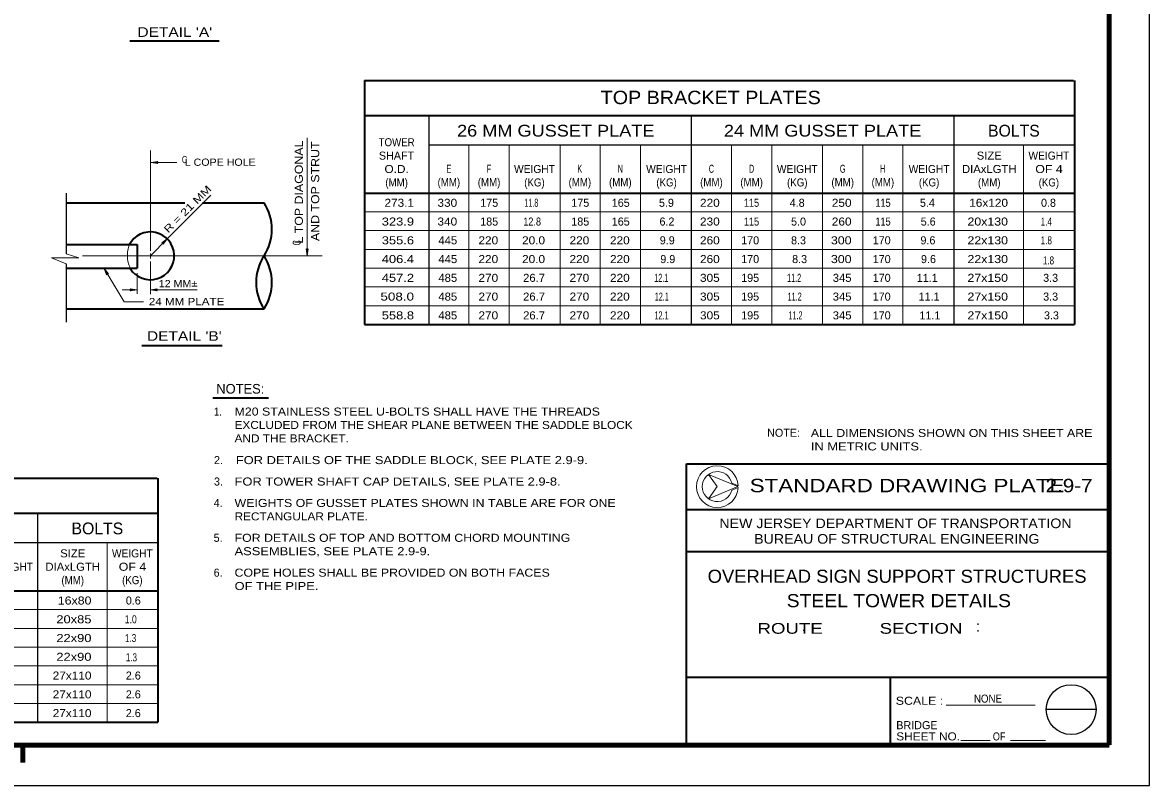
# Model space of a CAD drawing. Extents: x 312601.858 to 312602.699, y 144420.109 to 144420.704.
# Drawn here: x 312602.2782 to 312602.6988, y 144420.1095 to 144420.3942 of the extents above; entities that cross this region are included whole.
import ezdxf
from ezdxf.enums import TextEntityAlignment as Align

# ---------------------------------------------------------------- set-up
doc = ezdxf.new("R2010")
doc.units = 0
doc.header["$LTSCALE"] = 0.0012
doc.linetypes.add('DOT_DASHED', pattern=[7.7, 5, -1.2, 0.3, -1.2])
doc.linetypes.add('DOTTED', pattern=[1.5, 0.3, -1.2])
for name, color, linetype, lineweight in [('1', 7, 'Continuous', 25), ('2', 7, 'Continuous', 13), ('39', 7, 'Continuous', 13)]:
    doc.layers.add(name, color=color, linetype=linetype, lineweight=lineweight)
doc.layers.add('4', color=7, linetype='Continuous')

msp = doc.modelspace()

# ---------------------------------------------------------------- hatches: boundary and pattern name
at = {"layer": '39'}
for points in [[(312602.3284, 144420.3419), (312602.3287, 144420.3415), (312602.3261, 144420.3419), (312602.3287, 144420.3423)], [(312602.3306, 144420.3118), (312602.3301, 144420.3119), (312602.3322, 144420.3135), (312602.3307, 144420.3114)], [(312602.3844, 144420.3094), (312602.3848, 144420.3097), (312602.3844, 144420.3071), (312602.384, 144420.3097)], [(312602.3098, 144420.3004), (312602.3095, 144420.3), (312602.3086, 144420.3024), (312602.3102, 144420.3004)], [(312602.3186, 144420.2944), (312602.3184, 144420.2948), (312602.3209, 144420.2944), (312602.3184, 144420.294)], [(312602.3186, 144420.2944), (312602.3184, 144420.2948), (312602.3209, 144420.2944), (312602.3184, 144420.294)], [(312602.3282, 144420.2944), (312602.3284, 144420.294), (312602.3259, 144420.2944), (312602.3284, 144420.2948)]]:
    msp.add_hatch(color=256, dxfattribs=at).paths.add_polyline_path(points)

# ---------------------------------------------------------------- linework, layer by layer
at = {"layer": '1', "lineweight": 13}
for p, q in [((312602.3844, 144420.3511), (312602.3844, 144420.3071)), ((312602.3259, 144420.3464), (312602.3259, 144420.309)), ((312602.3357, 144420.3419), (312602.3262, 144420.3419)), ((312602.3259, 144420.308), (312602.3259, 144420.3061)), ((312602.3812, 144420.3071), (312602.3871, 144420.3071)), ((312602.3161, 144420.2899), (312602.3086, 144420.3024)), ((312602.3259, 144420.305), (312602.3259, 144420.2928)), ((312602.3209, 144420.3007), (312602.3209, 144420.2929)), ((312602.3209, 144420.2944), (312602.3154, 144420.2944)), ((312602.3433, 144420.2944), (312602.3259, 144420.2944)), ((312602.3434, 144420.2958), (312602.3414, 144420.2958)), ((312602.3233, 144420.2899), (312602.3161, 144420.2899)), ((312602.543, 144420.2197), (312602.5453, 144420.2207))]:
    msp.add_line(p, q, dxfattribs=at)
at = {"layer": '1'}
for p, q in [((312602.2944, 144420.3305), (312602.2944, 144420.3079)), ((312602.2944, 144420.3041), (312602.2944, 144420.2823))]:
    msp.add_line(p, q, dxfattribs=at)
at = {"layer": '1', "lineweight": 35}
for p, q in [((312602.2944, 144420.3269), (312602.3387, 144420.3269)), ((312602.3453, 144420.3269), (312602.3683, 144420.3269)), ((312602.2944, 144420.3113), (312602.3209, 144420.3113)), ((312602.3209, 144420.3113), (312602.3209, 144420.3025)), ((312602.2944, 144420.3025), (312602.3209, 144420.3025)), ((312602.2944, 144420.2873), (312602.3683, 144420.2873))]:
    msp.add_line(p, q, dxfattribs=at)
at = {"layer": '1', "linetype": 'DOT_DASHED', "lineweight": 13}
msp.add_line((312602.3005, 144420.3071), (312602.39, 144420.3071), dxfattribs=at)
at = {"layer": '1', "lineweight": 158}
msp.add_line((312602.2783, 144420.1181), (312602.2783, 144420.1245), dxfattribs=at)
at = {"layer": '1', "lineweight": 13}
for points in [[(312602.3259, 144420.3071), (312602.3322, 144420.3135), (312602.3484, 144420.3297)], [(312602.2944, 144420.3041), (312602.289, 144420.3063), (312602.2992, 144420.3063), (312602.2944, 144420.3079)], [(312602.5451, 144420.221), (312602.5342, 144420.2255), (312602.5451, 144420.221)], [(312602.5453, 144420.2213), (312602.543, 144420.2223), (312602.5429, 144420.2223)]]:
    msp.add_lwpolyline(points, dxfattribs=at)
for points in [[(312602.5451, 144420.221), (312602.5342, 144420.2255), (312602.5374, 144420.221), (312602.5342, 144420.2165)], [(312602.5374, 144420.221), (312602.5342, 144420.2165), (312602.5451, 144420.221), (312602.5342, 144420.2255)]]:
    msp.add_lwpolyline(points, close=True, dxfattribs=at)
at = {"layer": '1', "lineweight": 35}
for centre, radius, start, end in [((312602.353043, 144420.317), 0.018187, 327.02071, 32.97929), ((312602.3259, 144420.3071), 0.008914, 212.2085, 152.57299), ((312602.383557, 144420.2972), 0.018187, 147.02071, 212.97929), ((312602.353043, 144420.2972), 0.018187, 327.02071, 32.97929)]:
    msp.add_arc(centre, radius, start, end, dxfattribs=at)
at = {"layer": '1', "linetype": 'DOTTED', "lineweight": 13}
msp.add_arc((312602.328025, 144420.307233), 0.010726, 157.7196, 206.18542, dxfattribs=at)
at = {"layer": '1', "lineweight": 13}
for radius, start, end in [(0.007803, 2.21392, 357.78608), (0.0056, 13.69411, 346.30589)]:
    msp.add_arc((312602.5375, 144420.221), radius, start, end, dxfattribs=at)
at = {"layer": '2', "lineweight": 35}
for p, q in [((312602.3182, 144420.3873), (312602.3516, 144420.3873)), ((312602.4058, 144420.3725), (312602.4058, 144420.2815)), ((312602.4058, 144420.3725), (312602.6705, 144420.3725)), ((312602.6708, 144420.3725), (312602.6708, 144420.2815)), ((312602.4058, 144420.3595), (312602.6708, 144420.3595)), ((312602.4058, 144420.3305), (312602.6708, 144420.3305)), ((312602.4058, 144420.2815), (312602.6708, 144420.2815)), ((312602.3227, 144420.2737), (312602.3527, 144420.2737)), ((312602.37, 144420.254), (312602.3492, 144420.254)), ((312602.0147, 144420.2241), (312602.3284, 144420.2241)), ((312602.3287, 144420.2241), (312602.3287, 144420.1331)), ((312602.0147, 144420.2111), (312602.3287, 144420.2111)), ((312602.0147, 144420.1821), (312602.3287, 144420.1821)), ((312602.0147, 144420.1331), (312602.3287, 144420.1331))]:
    msp.add_line(p, q, dxfattribs=at)
at = {"layer": '2'}
for p, q in [((312602.4058, 144420.3725), (312602.4058, 144420.2815)), ((312602.4448, 144420.3485), (312602.4448, 144420.2815)), ((312602.4598, 144420.3485), (312602.4598, 144420.2815)), ((312602.4788, 144420.3485), (312602.4788, 144420.2815)), ((312602.4938, 144420.3485), (312602.4938, 144420.2815)), ((312602.5088, 144420.3485), (312602.5088, 144420.2815)), ((312602.5428, 144420.3485), (312602.5428, 144420.2815)), ((312602.5578, 144420.3485), (312602.5578, 144420.2815)), ((312602.5768, 144420.3485), (312602.5768, 144420.2815)), ((312602.5918, 144420.3485), (312602.5918, 144420.2815)), ((312602.6068, 144420.3485), (312602.6068, 144420.2815)), ((312602.6518, 144420.3485), (312602.6518, 144420.2815)), ((312602.4058, 144420.3235), (312602.6708, 144420.3235)), ((312602.4058, 144420.3165), (312602.6708, 144420.3165)), ((312602.4058, 144420.3095), (312602.6705, 144420.3095)), ((312602.4058, 144420.3025), (312602.6708, 144420.3025)), ((312602.4058, 144420.2955), (312602.6708, 144420.2955)), ((312602.4058, 144420.2885), (312602.6708, 144420.2885)), ((312602.3097, 144420.2001), (312602.3097, 144420.1331)), ((312602.0147, 144420.1751), (312602.3287, 144420.1751)), ((312602.0147, 144420.1681), (312602.3287, 144420.1681)), ((312602.0147, 144420.1611), (312602.3284, 144420.1611)), ((312602.0147, 144420.1541), (312602.3287, 144420.1541)), ((312602.0147, 144420.1471), (312602.3287, 144420.1471)), ((312602.0147, 144420.1401), (312602.3287, 144420.1401))]:
    msp.add_line(p, q, dxfattribs=at)
at = {"layer": '2', "lineweight": 25}
for p, q in [((312602.4298, 144420.3595), (312602.4298, 144420.2815)), ((312602.5278, 144420.3595), (312602.5278, 144420.2815)), ((312602.6258, 144420.3595), (312602.6258, 144420.2815)), ((312602.4298, 144420.3485), (312602.6708, 144420.3485)), ((312602.2837, 144420.2111), (312602.2837, 144420.1331)), ((312602.0387, 144420.2001), (312602.3287, 144420.2001))]:
    msp.add_line(p, q, dxfattribs=at)
at = {"layer": '39', "lineweight": 25}
for p, q in [((312602.6988, 144420.1095), (312602.6988, 144420.7035)), ((312602.6789, 144420.1378), (312602.6603, 144420.1378)), ((312602.452, 144420.1245), (312602.6838, 144420.1245)), ((312601.8578, 144420.1095), (312602.6988, 144420.1095))]:
    msp.add_line(p, q, dxfattribs=at)
at = {"layer": '39', "lineweight": 158}
for p, q in [((312602.6838, 144420.1247), (312602.6838, 144420.6645)), ((312601.9088, 144420.1245), (312602.6838, 144420.1245)), ((312602.2783, 144420.1181), (312602.2783, 144420.1245))]:
    msp.add_line(p, q, dxfattribs=at)
at = {"layer": '39', "lineweight": 35}
for p, q in [((312602.526, 144420.1245), (312602.526, 144420.2295)), ((312602.526, 144420.2295), (312602.6838, 144420.2295)), ((312602.6838, 144420.2295), (312602.6838, 144420.1245)), ((312602.526, 144420.2124), (312602.6838, 144420.2124)), ((312602.526, 144420.1968), (312602.6838, 144420.1968)), ((312602.526, 144420.1499), (312602.6838, 144420.1499)), ((312602.6022, 144420.1248), (312602.6022, 144420.1499))]:
    msp.add_line(p, q, dxfattribs=at)
at = {"layer": '39'}
for p, q in [((312602.6022, 144420.1499), (312602.6838, 144420.1499)), ((312602.6022, 144420.1248), (312602.6022, 144420.1499)), ((312602.6022, 144420.1248), (312602.6022, 144420.1499)), ((312602.6229, 144420.1395), (312602.6561, 144420.1395)), ((312602.6284, 144420.1263), (312602.6394, 144420.1263)), ((312602.6469, 144420.1263), (312602.66, 144420.1263))]:
    msp.add_line(p, q, dxfattribs=at)
for points in [[(312602.3284, 144420.3419), (312602.3287, 144420.3415), (312602.3261, 144420.3419), (312602.3287, 144420.3423)], [(312602.3306, 144420.3118), (312602.3301, 144420.3119), (312602.3322, 144420.3135), (312602.3307, 144420.3114)], [(312602.3844, 144420.3094), (312602.3848, 144420.3097), (312602.3844, 144420.3071), (312602.384, 144420.3097)], [(312602.3098, 144420.3004), (312602.3095, 144420.3), (312602.3086, 144420.3024), (312602.3102, 144420.3004)], [(312602.3186, 144420.2944), (312602.3184, 144420.2948), (312602.3209, 144420.2944), (312602.3184, 144420.294)], [(312602.3186, 144420.2944), (312602.3184, 144420.2948), (312602.3209, 144420.2944), (312602.3184, 144420.294)], [(312602.3282, 144420.2944), (312602.3284, 144420.294), (312602.3259, 144420.2944), (312602.3284, 144420.2948)], [(312602.5451, 144420.221), (312602.5342, 144420.2255), (312602.5374, 144420.221), (312602.5342, 144420.2165)]]:
    msp.add_lwpolyline(points, close=True, dxfattribs=at)
at = {"layer": '39', "lineweight": 25}
msp.add_circle((312602.6696, 144420.1378), 0.0093, dxfattribs=at)

# ---------------------------------------------------------------- texts
at = {"layer": '1'}
msp.add_text('6.', height=0.003, dxfattribs=at).set_placement((312602.3495, 144420.1874))
for s, width, p in [('COPE HOLES SHALL BE PROVIDED ON BOTH FACES', 1.15, (312602.3573, 144420.1874)), ('OF THE PIPE.', 1.2, (312602.3573, 144420.1824))]:
    msp.add_text(s, height=0.003, dxfattribs=dict(at, width=width)).set_placement(p)
at = {"layer": '2'}
for s, height, width, p in [("DETAIL 'A'", 0.0036, 1.2, (312602.335, 144420.3888)), ('TOP BRACKET PLATES', 0.005, 1.1, (312602.53505, 144420.3637)), ('26 MM GUSSET PLATE', 0.0044, 1.15, (312602.4772, 144420.3516)), ('24 MM GUSSET PLATE', 0.0044, 1.15, (312602.5768, 144420.3516)), ('TOWER', 0.003, 0.9, (312602.4178, 144420.348)), ('C', 0.0027, 0.65, (312602.33865, 144420.3417)), ('L COPE HOLE', 0.0027, 1.1, (312602.35195, 144420.3407)), ('SIZE', 0.003, 1.05, (312602.639, 144420.343)), ('WEIGHT', 0.003, 0.95, (312602.66125, 144420.343)), ('O.D.', 0.003, 1.1, (312602.4178, 144420.338)), ('E', 0.003, 0.7, (312602.4373, 144420.3381)), ('F', 0.003, 0.7, (312602.45225, 144420.3381)), ('WEIGHT', 0.003, 0.95, (312602.46925, 144420.338)), ('K', 0.003, 0.65, (312602.48615, 144420.3381)), ('N', 0.003, 0.6, (312602.5013, 144420.3381)), ('WEIGHT', 0.003, 0.95, (312602.51855, 144420.338)), ('C', 0.003, 0.6, (312602.5353, 144420.3381)), ('D', 0.003, 0.6, (312602.5503, 144420.3381)), ('WEIGHT', 0.003, 0.95, (312602.56735, 144420.338)), ('G', 0.003, 0.6, (312602.5843, 144420.3381)), ('H', 0.003, 0.6, (312602.59925, 144420.3381)), ('WEIGHT', 0.003, 0.95, (312602.61655, 144420.338)), ('DIAxLGTH', 0.003, 1.05, (312602.639, 144420.338)), ('OF 4', 0.003, 1.15, (312602.6613, 144420.338)), ('(MM)', 0.003, 0.9, (312602.4178, 144420.333)), ('(MM)', 0.003, 0.9, (312602.4373, 144420.3331)), ('(MM)', 0.003, 0.9, (312602.4523, 144420.3331)), ('(KG)', 0.003, 0.9, (312602.46925, 144420.333)), ('(MM)', 0.003, 0.9, (312602.4862, 144420.3331)), ('(MM)', 0.003, 0.9, (312602.5013, 144420.3331)), ('(KG)', 0.003, 0.9, (312602.51855, 144420.333)), ('(MM)', 0.003, 0.9, (312602.5353, 144420.3331)), ('(MM)', 0.003, 0.9, (312602.5503, 144420.3331)), ('(KG)', 0.003, 0.9, (312602.56735, 144420.333)), ('(MM)', 0.003, 0.9, (312602.5843, 144420.3331)), ('(MM)', 0.003, 0.9, (312602.5993, 144420.3331)), ('(KG)', 0.003, 0.9, (312602.61655, 144420.333)), ('(MM)', 0.003, 0.9, (312602.639, 144420.333)), ('(KG)', 0.003, 0.9, (312602.66125, 144420.333)), ('12 MM+', 0.0027, 1.1, (312602.33625, 144420.2954)), ('24 MM PLATE', 0.0027, 1.2, (312602.3394, 144420.2887)), ("DETAIL 'B'", 0.0036, 1.2, (312602.33855, 144420.2754)), ('1.', 0.003, 0.9, (312602.3511, 144420.2475)), ('FOR DETAILS OF THE SADDLE BLOCK, SEE PLATE 2.9-9.', 0.003, 1.2, (312602.42345, 144420.2294)), ('2.9-7', 0.005, 1.15, (312602.6688, 144420.2189)), ('SIZE', 0.003, 1.05, (312602.2969, 144420.1946)), ('WEIGHT', 0.003, 0.95, (312602.31915, 144420.1946)), ('WEIGHT', 0.003, 0.95, (312602.27445, 144420.1896)), ('DIAxLGTH', 0.003, 1.05, (312602.2969, 144420.1896)), ('OF 4', 0.003, 1.15, (312602.3192, 144420.1896)), ('(MM)', 0.003, 0.9, (312602.2969, 144420.1846)), ('(KG)', 0.003, 0.9, (312602.31915, 144420.1846)), ('OVERHEAD SIGN SUPPORT STRUCTURES', 0.0049, 1.05, (312602.6046, 144420.1851)), ('STEEL TOWER DETAILS', 0.0049, 1.1, (312602.60525, 144420.176))]:
    msp.add_text(s, height=height, dxfattribs=dict(at, width=width)).set_placement(p, align=Align.CENTER)
for s, height, p in [('BOLTS', 0.0044, (312602.6482, 144420.3516)), ('SHAFT', 0.003, (312602.41775, 144420.343)), ('NOTES:', 0.0036, (312602.35945, 144420.2557)), ('2.', 0.003, (312602.3513, 144420.2294)), ('3.', 0.003, (312602.3513, 144420.2214)), ('BOLTS', 0.0044, (312602.3061, 144420.2032))]:
    msp.add_text(s, height=height, dxfattribs=at).set_placement(p, align=Align.CENTER)
for s, height, rotation, width, p in [('L TOP DIAGONAL', 0.003, 90, 1.15, (312602.3828, 144420.3309)), ('AND TOP STRUT', 0.003, 90, 1.15, (312602.3889, 144420.3312)), ('R = 21 MM', 0.0027, 45, 1.3, (312602.340695, 144420.323595)), ('C', 0.003, 90, 0.6, (312602.382, 144420.312))]:
    msp.add_text(s, height=height, rotation=rotation, dxfattribs=dict(at, width=width)).set_placement(p, align=Align.CENTER)
for s, width, p in [('273.1', 1.1, (312602.4243, 144420.3254)), ('330', 1.1, (312602.4404, 144420.3254)), ('11.8', 0.65, (312602.4707, 144420.3254)), ('220', 1.1, (312602.5384, 144420.3254)), ('115', 0.85, (312602.5531, 144420.3254)), ('250', 1.1, (312602.5876, 144420.3254)), ('115', 0.85, (312602.6022, 144420.3254)), ('16x120', 1.1, (312602.646, 144420.3254)), ('323.9', 1.2, (312602.4243, 144420.3184)), ('340', 1.1, (312602.4404, 144420.3184)), ('12.8', 0.85, (312602.4717, 144420.3184)), ('230', 1.1, (312602.5384, 144420.3184)), ('115', 0.85, (312602.5531, 144420.3184)), ('260', 1.1, (312602.5876, 144420.3184)), ('115', 0.85, (312602.6022, 144420.3184)), ('20x130', 1.15, (312602.646, 144420.3184)), ('1.4', 0.75, (312602.6624, 144420.3184)), ('355.6', 1.2, (312602.4243, 144420.3114)), ('445', 1.05, (312602.4404, 144420.3114)), ('220', 1.1, (312602.4557, 144420.3114)), ('20.0', 1.1, (312602.4732, 144420.3114)), ('220', 1.1, (312602.4897, 144420.3114)), ('220', 1.1, (312602.5048, 144420.3114)), ('260', 1.1, (312602.5384, 144420.3114)), ('300', 1.15, (312602.5876, 144420.3114)), ('22x130', 1.15, (312602.646, 144420.3114)), ('1.8', 0.75, (312602.6624, 144420.3114)), ('406.4', 1.2, (312602.4243, 144420.3044)), ('445', 1.05, (312602.4404, 144420.3044)), ('220', 1.1, (312602.4557, 144420.3044)), ('20.0', 1.1, (312602.4732, 144420.3044)), ('220', 1.1, (312602.4897, 144420.3044)), ('220', 1.1, (312602.5048, 144420.3044)), ('260', 1.1, (312602.5384, 144420.3044)), ('300', 1.15, (312602.5876, 144420.3044)), ('22x130', 1.15, (312602.646, 144420.3044)), ('1.8', 0.75, (312602.6632, 144420.3039)), ('457.2', 1.2, (312602.4243, 144420.2974)), ('485', 1.05, (312602.4404, 144420.2974)), ('270', 1.1, (312602.4557, 144420.2974)), ('26.7', 1.05, (312602.4732, 144420.2974)), ('270', 1.1, (312602.4897, 144420.2974)), ('220', 1.1, (312602.5048, 144420.2974)), ('12.1', 0.65, (312602.5192, 144420.2974)), ('305', 1.1, (312602.5384, 144420.2974)), ('11.2', 0.65, (312602.5688, 144420.2974)), ('345', 1.05, (312602.5876, 144420.2974)), ('27x150', 1.15, (312602.646, 144420.2974)), ('508.0', 1.25, (312602.4243, 144420.2904)), ('485', 1.05, (312602.4404, 144420.2904)), ('270', 1.1, (312602.4557, 144420.2904)), ('26.7', 1.05, (312602.4732, 144420.2904)), ('270', 1.1, (312602.4897, 144420.2904)), ('220', 1.1, (312602.5048, 144420.2904)), ('12.1', 0.65, (312602.5194, 144420.2904)), ('305', 1.1, (312602.5384, 144420.2904)), ('11.2', 0.65, (312602.569, 144420.2904)), ('345', 1.05, (312602.5876, 144420.2904)), ('27x150', 1.15, (312602.646, 144420.2904)), ('558.8', 1.2, (312602.4243, 144420.2834)), ('485', 1.05, (312602.4404, 144420.2834)), ('270', 1.1, (312602.4557, 144420.2834)), ('26.7', 1.05, (312602.4732, 144420.2834)), ('270', 1.1, (312602.4897, 144420.2834)), ('220', 1.1, (312602.5048, 144420.2834)), ('12.1', 0.65, (312602.5193, 144420.2834)), ('305', 1.1, (312602.5384, 144420.2834)), ('11.2', 0.65, (312602.5693, 144420.2834)), ('345', 1.05, (312602.5876, 144420.2834)), ('27x150', 1.15, (312602.646, 144420.2834)), ('16x80', 1.15, (312602.3039, 144420.177)), ('20x85', 1.2, (312602.3039, 144420.17)), ('1.0', 0.8, (312602.3208, 144420.17)), ('22x90', 1.2, (312602.3039, 144420.163)), ('1.3', 0.75, (312602.3206, 144420.163)), ('22x90', 1.2, (312602.3039, 144420.156)), ('1.3', 0.75, (312602.3209, 144420.1558)), ('27x110', 1.1, (312602.3039, 144420.149)), ('27x110', 1.1, (312602.3039, 144420.142)), ('27x110', 1.1, (312602.3039, 144420.135))]:
    msp.add_text(s, height=0.003, dxfattribs=dict(at, width=width)).set_placement(p, align=Align.RIGHT)
for s, p in [('175', (312602.4557, 144420.3254)), ('175', (312602.4897, 144420.3254)), ('165', (312602.5048, 144420.3254)), ('5.9', (312602.5213, 144420.3254)), ('4.8', (312602.5701, 144420.3254)), ('5.4', (312602.6187, 144420.3254)), ('0.8', (312602.6639, 144420.3254)), ('185', (312602.4557, 144420.3184)), ('185', (312602.4897, 144420.3184)), ('165', (312602.5048, 144420.3184)), ('6.2', (312602.5215, 144420.3184)), ('5.0', (312602.5706, 144420.3184)), ('5.6', (312602.619, 144420.3184)), ('9.9', (312602.5216, 144420.3114)), ('170', (312602.5531, 144420.3114)), ('8.3', (312602.5706, 144420.3114)), ('170', (312602.6022, 144420.3114)), ('9.6', (312602.6189, 144420.3114)), ('9.9', (312602.5218, 144420.3044)), ('170', (312602.5531, 144420.3044)), ('8.3', (312602.571, 144420.3044)), ('170', (312602.6022, 144420.3044)), ('9.6', (312602.6191, 144420.3044)), ('195', (312602.5531, 144420.2974)), ('170', (312602.6022, 144420.2974)), ('11.1', (312602.619757, 144420.2974)), ('3.3', (312602.6647, 144420.2974)), ('195', (312602.5531, 144420.2904)), ('170', (312602.6022, 144420.2904)), ('11.1', (312602.620457, 144420.2904)), ('3.3', (312602.6647, 144420.2904)), ('195', (312602.5531, 144420.2834)), ('170', (312602.6022, 144420.2834)), ('11.1', (312602.620757, 144420.2834)), ('3.3', (312602.665, 144420.2834)), ('0.6', (312602.3223, 144420.177)), ('2.6', (312602.3223, 144420.149)), ('2.6', (312602.3223, 144420.142)), ('2.6', (312602.3223, 144420.135))]:
    msp.add_text(s, height=0.003, dxfattribs=at).set_placement(p, align=Align.RIGHT)
for s, width, p in [('M20 STAINLESS STEEL U-BOLTS SHALL HAVE THE THREADS', 1.15, (312602.3573, 144420.2475)), ('EXCLUDED FROM THE SHEAR PLANE BETWEEN THE SADDLE BLOCK', 1.1, (312602.3573, 144420.2425)), ('AND THE BRACKET.', 1.1, (312602.3573, 144420.2375)), ('FOR TOWER SHAFT CAP DETAILS, SEE PLATE 2.9-8.', 1.2, (312602.3573, 144420.2214)), ('WEIGHTS OF GUSSET PLATES SHOWN IN TABLE ARE FOR ONE', 1.15, (312602.3573, 144420.2134)), ('RECTANGULAR PLATE.', 1.1, (312602.3573, 144420.2084)), ('FOR DETAILS OF TOP AND BOTTOM CHORD MOUNTING', 1.15, (312602.3573, 144420.2004)), ('ASSEMBLIES, SEE PLATE 2.9-9.', 1.2, (312602.3573, 144420.1954)), ('NONE', 0.9, (312602.6333, 144420.1404))]:
    msp.add_text(s, height=0.003, dxfattribs=dict(at, width=width)).set_placement(p)
for s, p in [('4.', (312602.3495, 144420.2134)), ('5.', (312602.3495, 144420.2004))]:
    msp.add_text(s, height=0.003, dxfattribs=at).set_placement(p)
at = {"layer": '39'}
for s, height, width, p in [('STANDARD DRAWING PLATE       ', 0.005, 1.25, (312602.61645, 144420.2189)), ('NEW JERSEY DEPARTMENT OF TRANSPORTATION', 0.003599, 1.1, (312602.604, 144420.2055)), ('BUREAU OF STRUCTURAL ENGINEERING', 0.0036, 1.1, (312602.6045, 144420.1997)), ('ROUTE           SECTION', 0.004, 1.3, (312602.59075, 144420.1661)), ('SCALE :', 0.003, 1.15, (312602.61295, 144420.1396)), ('OF', 0.003, 0.85, (312602.6427, 144420.1263))]:
    msp.add_text(s, height=height, dxfattribs=dict(at, width=width)).set_placement(p, align=Align.CENTER)
for p in [(312602.569737, 144420.1671), (312602.634837, 144420.1669)]:
    msp.add_text(':', height=0.004, dxfattribs=at).set_placement(p, align=Align.CENTER)
msp.add_text('BRIDGE', height=0.003, dxfattribs=at).set_placement((312602.6043, 144420.1305))
at = {"layer": '39', "width": 1.1}
msp.add_text('SHEET NO.', height=0.003, dxfattribs=at).set_placement((312602.6043, 144420.1263))
at = {"layer": '4'}
msp.add_text('NOTE:', height=0.003, dxfattribs=at).set_placement((312602.5561, 144420.2396))
for s, width, p in [('ALL DIMENSIONS SHOWN ON THIS SHEET ARE', 1.15, (312602.5724, 144420.2395)), ('IN METRIC UNITS.', 1.2, (312602.5724, 144420.2345))]:
    msp.add_text(s, height=0.003, dxfattribs=dict(at, width=width)).set_placement(p)

doc.saveas('drawing.dxf')
